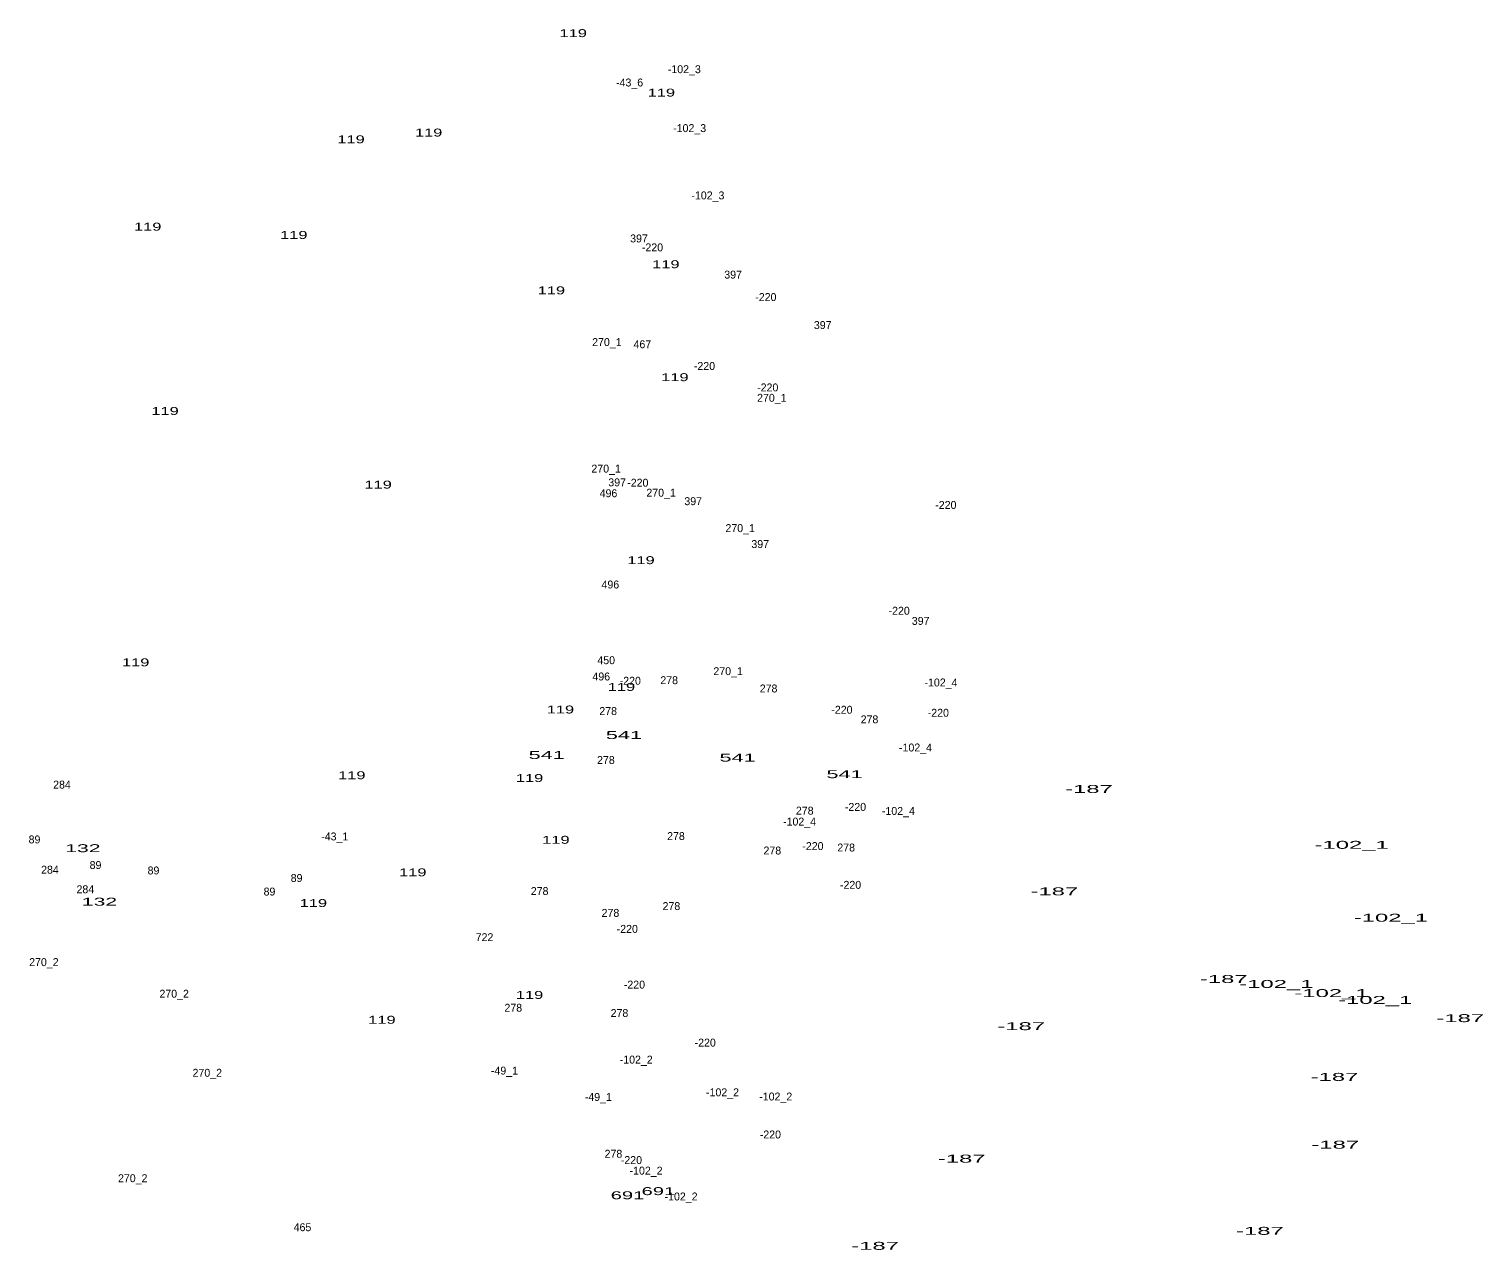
# Model space of a CAD drawing. Extents: x -658595 to -655205, y -1004347 to -1000147.
# Drawn here: x -656079 to -655345, y -1002225 to -1001609 of the extents above; entities that cross this region are included whole.
import ezdxf
from ezdxf.enums import TextEntityAlignment as Align

# ---------------------------------------------------------------- set-up
doc = ezdxf.new("R2010")
doc.units = 0
doc.header["$LTSCALE"] = 1.6
doc.layers.add('24', color=7, linetype='Continuous')

msp = doc.modelspace()

# ---------------------------------------------------------------- texts
at = {"layer": '24'}
for s, width, p in [('119', 1.55, (-655804.589, -1001612.58)), ('119', 1.55, (-655760.089, -1001642.64)), ('119', 1.55, (-655877.619, -1001662.81)), ('119', 1.55, (-655916.799, -1001666.23)), ('119', 1.55, (-656019.499, -1001710.37)), ('119', 1.55, (-655945.709, -1001714.56)), ('119', 1.55, (-655757.809, -1001729.34)), ('119', 1.55, (-655815.619, -1001742.55)), ('119', 1.55, (-655753.239, -1001786.42)), ('119', 1.55, (-656010.749, -1001803.5)), ('119', 1.55, (-655903.109, -1001840.71)), ('119', 1.55, (-655770.359, -1001878.88)), ('119', 1.55, (-656025.579, -1001930.51)), ('119', 1.55, (-655780.249, -1001942.93)), ('119', 1.55, (-655811.059, -1001954.34)), ('541', 2.05, (-655778.983, -1001967.24)), ('541', 2.05, (-655817.973, -1001977.32)), ('541', 2.05, (-655721.563, -1001978.65)), ('119', 1.55, (-655916.419, -1001987.56)), ('541', 2.05, (-655667.543, -1001987.02)), ('119', 1.55, (-655826.649, -1001988.97)), ('-187', 2.25, (-655544.105, -1001994.48)), ('132', 2, (-656052.227, -1002024.42)), ('119', 1.55, (-655813.339, -1002020.17)), ('-102_1', 2.25, (-655411.444, -1002022.72)), ('119', 1.55, (-655885.609, -1002036.63)), ('-187', 2.25, (-655561.595, -1002046.23)), ('132', 2, (-656043.857, -1002051.44)), ('119', 1.55, (-655935.819, -1002052.13)), ('-102_1', 2.25, (-655391.624, -1002059.54)), ('-187', 2.25, (-655476.025, -1002090.51)), ('119', 1.55, (-655826.649, -1002098.55)), ('-102_1', 2.25, (-655449.464, -1002093.02)), ('-102_1', 2.25, (-655421.624, -1002097.63)), ('-102_1', 2.25, (-655399.544, -1002101.09)), ('119', 1.55, (-655901.199, -1002111.11)), ('-187', 2.25, (-655356.585, -1002110.29)), ('-187', 2.25, (-655578.335, -1002114.34)), ('-187', 2.25, (-655420.105, -1002139.97)), ('-187', 2.25, (-655419.725, -1002174.22)), ('-187', 2.25, (-655608.385, -1002181.27)), ('691', 1.9, (-655777.167, -1002199.79)), ('691', 1.9, (-655761.577, -1002197.7)), ('-187', 2.25, (-655457.765, -1002217.77)), ('-187', 2.25, (-655652.125, -1002225.35))]:
    msp.add_text(s, height=4, dxfattribs=dict(at, width=width)).set_placement(p, align=Align.CENTER)
for s, p in [('-102_3', (-655748.47, -1001630.8)), ('-43_6', (-655776.122, -1001637.52)), ('-102_3', (-655745.79, -1001660.57)), ('-102_3', (-655736.57, -1001694.57)), ('397', (-655771.378, -1001716.32)), ('-220', (-655764.549, -1001720.83)), ('397', (-655723.838, -1001734.59)), ('-220', (-655707.299, -1001745.94)), ('397', (-655678.578, -1001760.08)), ('270_1', (-655787.588, -1001768.69)), ('467', (-655769.663, -1001769.79)), ('-220', (-655738.299, -1001780.76)), ('-220', (-655706.349, -1001791.6)), ('270_1', (-655704.288, -1001796.85)), ('270_1', (-655787.968, -1001832.62)), ('397', (-655782.408, -1001839.56)), ('-220', (-655771.959, -1001839.74)), ('496', (-655786.783, -1001845.07)), ('270_1', (-655760.208, -1001844.79)), ('397', (-655743.998, -1001849.07)), ('-220', (-655616.389, -1001850.97)), ('270_1', (-655720.268, -1001862.68)), ('397', (-655710.148, -1001870.76)), ('496', (-655785.823, -1001891.17)), ('-220', (-655639.969, -1001904.43)), ('397', (-655629.128, -1001909.57)), ('450', (-655787.935, -1001929.43)), ('270_1', (-655726.358, -1001934.97)), ('496', (-655790.423, -1001937.65)), ('-220', (-655775.759, -1001939.82)), ('278', (-655756.133, -1001939.53)), ('278', (-655705.923, -1001943.71)), ('-102_4', (-655618.854, -1001940.68)), ('278', (-655786.943, -1001955.13)), ('-220', (-655668.879, -1001954.47)), ('-220', (-655620.189, -1001955.99)), ('278', (-655654.953, -1001959.31)), ('-102_4', (-655631.714, -1001973.53)), ('278', (-655788.083, -1001979.86)), ('284', (-656062.791, -1001992.29)), ('278', (-655687.663, -1002005.43)), ('-220', (-655662.029, -1002003.55)), ('-102_4', (-655640.354, -1002005.6)), ('-102_4', (-655690.274, -1002010.96)), ('89', (-656076.663, -1002019.99)), ('-43_1', (-655925.01, -1002018.48)), ('278', (-655752.703, -1002018.29)), ('-220', (-655683.519, -1002023.34)), ('278', (-655666.743, -1002024.07)), ('278', (-655704.023, -1002025.59)), ('284', (-656068.871, -1002035.28)), ('89', (-656045.853, -1002032.93)), ('89', (-656016.563, -1002035.67)), ('89', (-655944.293, -1002039.48)), ('284', (-656050.991, -1002045.17)), ('89', (-655957.993, -1002046.33)), ('278', (-655821.553, -1002046.07)), ('-220', (-655664.509, -1002042.94)), ('278', (-655754.993, -1002053.68)), ('278', (-655785.793, -1002057.1)), ('-220', (-655777.279, -1002065.19)), ('722', (-655849.383, -1002069.38)), ('270_2', (-656071.934, -1002081.97)), ('270_2', (-656006.134, -1002097.95)), ('-220', (-655773.669, -1002093.35)), ('278', (-655834.863, -1002105.04)), ('278', (-655781.233, -1002107.71)), ('-220', (-655737.919, -1002122.65)), ('-102_2', (-655772.78, -1002131.25)), ('270_2', (-655989.394, -1002137.9)), ('-49_1', (-655839.306, -1002136.79)), ('-102_2', (-655729.19, -1002147.77)), ('-102_2', (-655702.31, -1002149.89)), ('-49_1', (-655791.906, -1002150.13)), ('-220', (-655705.009, -1002169.07)), ('278', (-655784.273, -1002178.82)), ('-220', (-655775.189, -1002182)), ('270_2', (-656027.054, -1002191.17)), ('-102_2', (-655767.79, -1002187.34)), ('-102_2', (-655750.12, -1002200.4)), ('465', (-655941.317, -1002215.93))]:
    msp.add_text(s, height=4, dxfattribs=at).set_placement(p, align=Align.CENTER)

doc.saveas('drawing.dxf')
